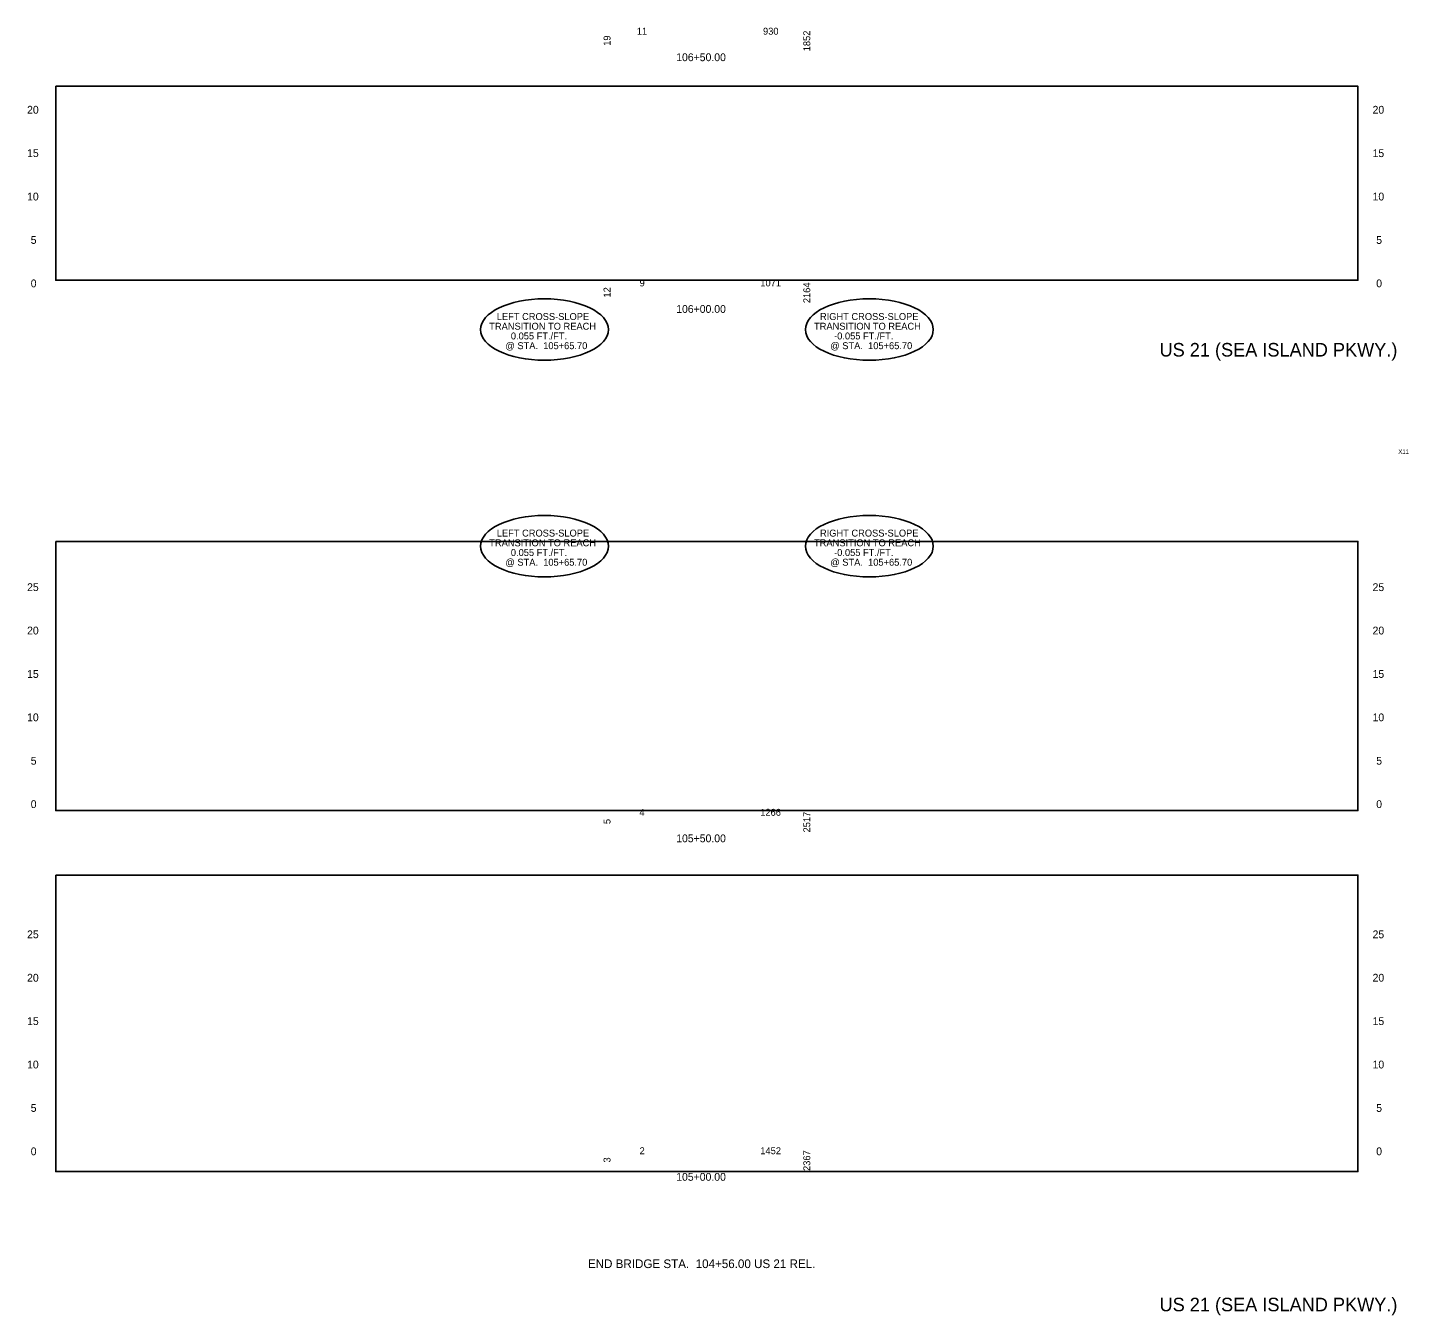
# Model space of a CAD drawing. Extents: x 971 to 1131, y 2203 to 6043.
# Drawn here: x 971.5 to 1130.5, y 4843.4 to 4991.8 of the extents above; entities that cross this region are included whole.
import ezdxf

# ---------------------------------------------------------------- set-up
doc = ezdxf.new("R2010")
doc.units = 0
for name, color, linetype in [('RD_SHT_Misc1', 7, 'Continuous'), ('RD_SHT_ShtClip', 7, 'Continuous'), ('RD_SHT_TX', 7, 'Continuous'), ('RD_TX_StaOff', 7, 'Continuous'), ('RD_XS_TX_Station', 7, 'Continuous')]:
    doc.layers.add(name, color=color, linetype=linetype)

msp = doc.modelspace()

# ---------------------------------------------------------------- linework, layer by layer
at = {"layer": 'RD_SHT_ShtClip'}
for points in [[(974.73, 4985.03), (1124.73, 4985.03), (1124.73, 4962.67), (974.73, 4962.67)], [(974.73, 4932.59), (1124.73, 4932.59), (1124.73, 4901.58), (974.73, 4901.58)], [(974.73, 4894.15), (1124.73, 4894.15), (1124.73, 4859.98), (974.73, 4859.98)]]:
    msp.add_lwpolyline(points, close=True, dxfattribs=at)
at = {"layer": 'RD_TX_StaOff'}
for centre in [(1031.02, 4957), (1068.45, 4957), (1031.02, 4932.04), (1068.45, 4932.04)]:
    msp.add_ellipse(centre, major_axis=(7.37, 0), ratio=0.480649, dxfattribs=at)

# ---------------------------------------------------------------- texts
at = {"layer": 'RD_SHT_Misc1'}
for s, p in [('11', (1041.66, 4990.97)), ('9', (1041.98, 4961.97)), ('1071', (1055.89, 4961.97)), ('4', (1041.97, 4900.98)), ('1266', (1055.88, 4900.98)), ('2', (1041.98, 4861.99)), ('1452', (1055.89, 4861.99))]:
    msp.add_text(s, height=0.8, dxfattribs=at).set_placement(p)
for s, rotation, p in [('930', 360, (1056.2, 4990.97)), ('19', 90, (1038.63, 4989.69)), ('1852', 90, (1061.64, 4989.06)), ('12', 90, (1038.63, 4960.69)), ('2164', 90, (1061.64, 4960.04)), ('2517', 90, (1061.64, 4899.06)), ('5', 90, (1038.63, 4900.02)), ('3', 90, (1038.63, 4861.03)), ('2367', 90, (1061.64, 4860.06))]:
    msp.add_text(s, height=0.8, rotation=rotation, dxfattribs=at).set_placement(p)
at = {"layer": 'RD_SHT_TX'}
for s, height, p in [('20', 0.9, (971.42, 4981.87)), ('20', 0.9, (1126.42, 4981.87)), ('15', 0.9, (971.42, 4976.87)), ('15', 0.9, (1126.42, 4976.87)), ('10', 0.9, (971.42, 4971.87)), ('10', 0.9, (1126.42, 4971.87)), ('5', 0.9, (971.84, 4966.87)), ('5', 0.9, (1126.84, 4966.87)), ('0', 0.9, (971.84, 4961.87)), ('0', 0.9, (1126.84, 4961.87)), ('US 21 (SEA ISLAND PKWY.)', 1.5625, (1101.88, 4953.89)), ('25', 0.9, (971.42, 4926.87)), ('25', 0.9, (1126.42, 4926.87)), ('20', 0.9, (971.42, 4921.87)), ('20', 0.9, (1126.42, 4921.87)), ('15', 0.9, (971.42, 4916.87)), ('15', 0.9, (1126.42, 4916.87)), ('10', 0.9, (971.42, 4911.87)), ('10', 0.9, (1126.42, 4911.87)), ('5', 0.9, (971.84, 4906.87)), ('5', 0.9, (1126.84, 4906.87)), ('0', 0.9, (971.84, 4901.87)), ('0', 0.9, (1126.84, 4901.87)), ('25', 0.9, (971.42, 4886.87)), ('25', 0.9, (1126.42, 4886.87)), ('20', 0.9, (971.42, 4881.87)), ('20', 0.9, (1126.42, 4881.87)), ('15', 0.9, (971.42, 4876.87)), ('15', 0.9, (1126.42, 4876.87)), ('10', 0.9, (971.42, 4871.87)), ('10', 0.9, (1126.42, 4871.87)), ('5', 0.9, (971.84, 4866.87)), ('5', 0.9, (1126.84, 4866.87)), ('0', 0.9, (971.84, 4861.87)), ('0', 0.9, (1126.84, 4861.87)), ('US 21 (SEA ISLAND PKWY.)', 1.5625, (1101.88, 4843.89))]:
    msp.add_text(s, height=height, dxfattribs=at).set_placement(p)
msp.add_text('X11', height=0.5, rotation=360, dxfattribs=at).set_placement((1129.39, 4942.68))
at = {"layer": 'RD_TX_StaOff'}
for s, height, p in [('LEFT CROSS-SLOPE', 0.8, (1025.53, 4958.1)), ('TRANSITION TO REACH', 0.8, (1024.66, 4956.98)), ('0.055 FT./FT.', 0.8, (1027.15, 4955.86)), ('@ STA.  105+65.70', 0.8, (1026.52, 4954.74)), ('TRANSITION TO REACH', 0.8, (1024.66, 4932.03)), ('LEFT CROSS-SLOPE', 0.8, (1025.53, 4933.15)), ('0.055 FT./FT.', 0.8, (1027.15, 4930.91)), ('@ STA.  105+65.70', 0.8, (1026.52, 4929.79)), ('END BRIDGE STA.  104+56.00 US 21 REL.', 1, (1036.03, 4848.87))]:
    msp.add_text(s, height=height, dxfattribs=at).set_placement(p)
for s, p in [('RIGHT CROSS-SLOPE', (1062.76, 4958.1)), ('TRANSITION TO REACH', (1062.08, 4956.98)), ('-0.055 FT./FT.', (1064.39, 4955.86)), ('@ STA.  105+65.70', (1063.95, 4954.74)), ('TRANSITION TO REACH', (1062.08, 4932.03)), ('RIGHT CROSS-SLOPE', (1062.76, 4933.15)), ('-0.055 FT./FT.', (1064.39, 4930.91)), ('@ STA.  105+65.70', (1063.95, 4929.79))]:
    msp.add_text(s, height=0.8, rotation=360, dxfattribs=at).set_placement(p)
at = {"layer": 'RD_XS_TX_Station'}
for s, p in [('106+50.00', (1046.2, 4987.92)), ('106+00.00', (1046.2, 4958.92)), ('105+50.00', (1046.2, 4897.93)), ('105+00.00', (1046.2, 4858.93))]:
    msp.add_text(s, height=0.9, dxfattribs=at).set_placement(p)

doc.saveas('drawing.dxf')
